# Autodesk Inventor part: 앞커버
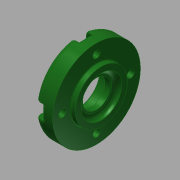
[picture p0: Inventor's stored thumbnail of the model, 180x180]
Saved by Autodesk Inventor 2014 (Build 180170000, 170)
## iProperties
Created: 2015-11
Part Number: 앞커버
Material: 알루미늄 6061
Document SubType Name: Modeling
Designer: mduedu
Density: 1 g/cm^3
Appearance: 매끄러움 - 짙은 산림 녹색
Author: mduedu
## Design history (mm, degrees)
sketch "스케치1"
  geometry: L1 (-7, 0)-(7, 0); L2 (-7, 0)-(-7, 27); L3 (-7, 27)-(4, 27); L4 (4, 27)-(4, 16); L5 (4, 16)-(7, 16); L6 (7, 16)-(7, 0); 2 further points
  constraints: 12 end point, 3 perpendicular, 2 parallel, 1 coincident, 1 horizontal, 1 midpoint
  dimensions: "d0" = 14 distance of L1.start L1.end; "d1" = 54 diameter of L3 L1; "d2" = 3 distance of L4.end L5.end; "d3" = 32 diameter of L5 L1
revolve "회전1" sketch "스케치1" stored, may be unused: angle "d4" = 90 deg
hole "구멍1" diameter "d7" = 25; stored, may be unused: countersink angle "d11" = 90 deg, drill point angle "d13" = 0 deg; dims "d5" = 10, "d6" = 10, "d8" = 6, "d9" = 4, "d10" = 2, "d12" = 3
hole "구멍2" diameter "d16" = 25; stored, may be unused: countersink angle "d20" = 90 deg, drill point angle "d22" = 0 deg; dims "d17" = 6, "d18" = 4, "d19" = 2, "d21" = 7.7, "d58" = 10, "d59" = 10
hole "구멍3" diameter "d25" = 17; stored, may be unused: countersink angle "d29" = 90 deg, drill point angle "d31" = 0 deg; dims "d23" = 10, "d24" = 10, "d26" = 6, "d27" = 4, "d28" = 2, "d30" = 4.2
chamfer "모따기1" distance "d32" = 0.6; stored, may be unused: second distance "d33" = 2, angle "d34" = 30 deg
fillet "모깎기1" dims "d35" = 0.3
fillet "모깎기2" dims "d36" = 3
fillet "모깎기3" dims "d37" = 3
fillet "모깎기4" dims "d38" = 0.3
sketch "스케치3" dims "d61" = 42
  geometry: C1 r 27 at (0, 0) reference; 2 further points
  constraints: 2 vertical alignment, 1 coincident, 2 other
hole "구멍4" sketch "스케치3" at (0, 21) diameter "d44" = 4.5; stored, may be unused: countersink angle "d48" = 90 deg, drill point angle "d50" = 0 deg; dims "d45" = 6, "d46" = 8, "d47" = 4.6, "d49" = 8
sketch "스케치4"
  geometry: L1 (-4, 5.702)-(-4, 0); L2 (4, 5.702)-(4, 0); A1 r 27 centre (0, -21) between (-4, 5.702) and (4, 5.702) reference; A2 r 4 centre (0, 0) between (-2.824, 2.833) and (2.824, 2.833) reference
  constraints: 4 end point, 4 point on circle, 2 tangent, 2 vertical
extrude "돌출1" cut sketch "스케치4" stored distance "d51" = 0; taper "d52" = 0 deg
fillet "모깎기5" dims "d56" = 0.3
fillet "모깎기6" dims "d57" = 1
node "솔리드1"
pattern_circular "원형 패턴2" dims angle "d64" = 360 deg
pattern_circular "원형 패턴1" dims angle "d54" = 360 deg
